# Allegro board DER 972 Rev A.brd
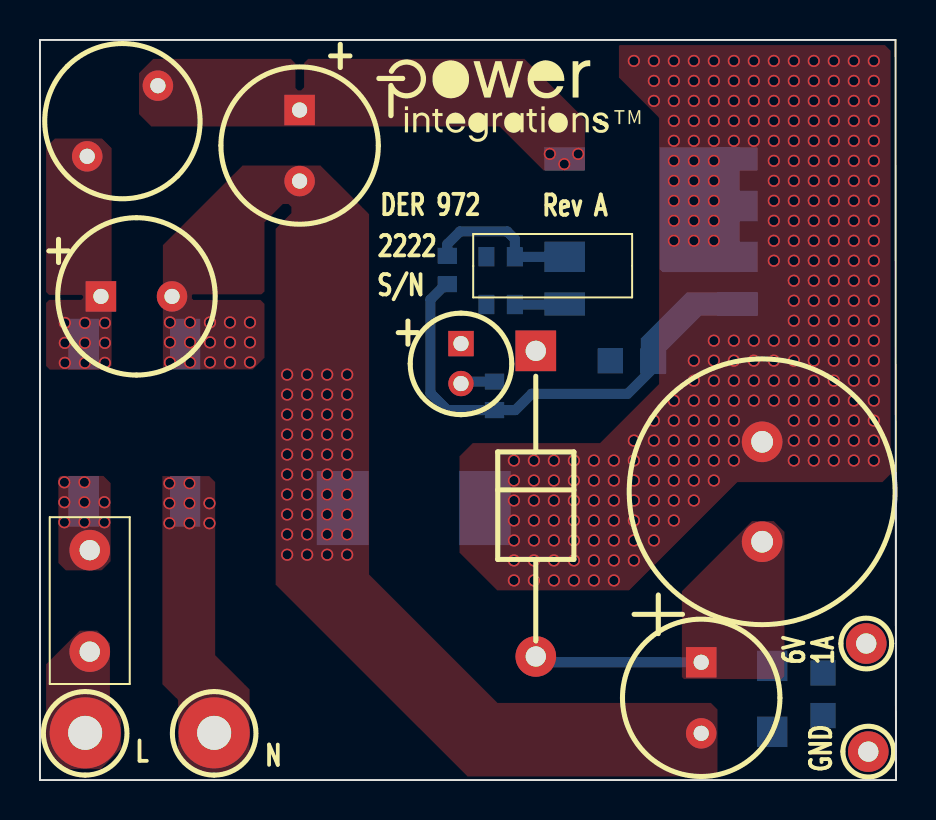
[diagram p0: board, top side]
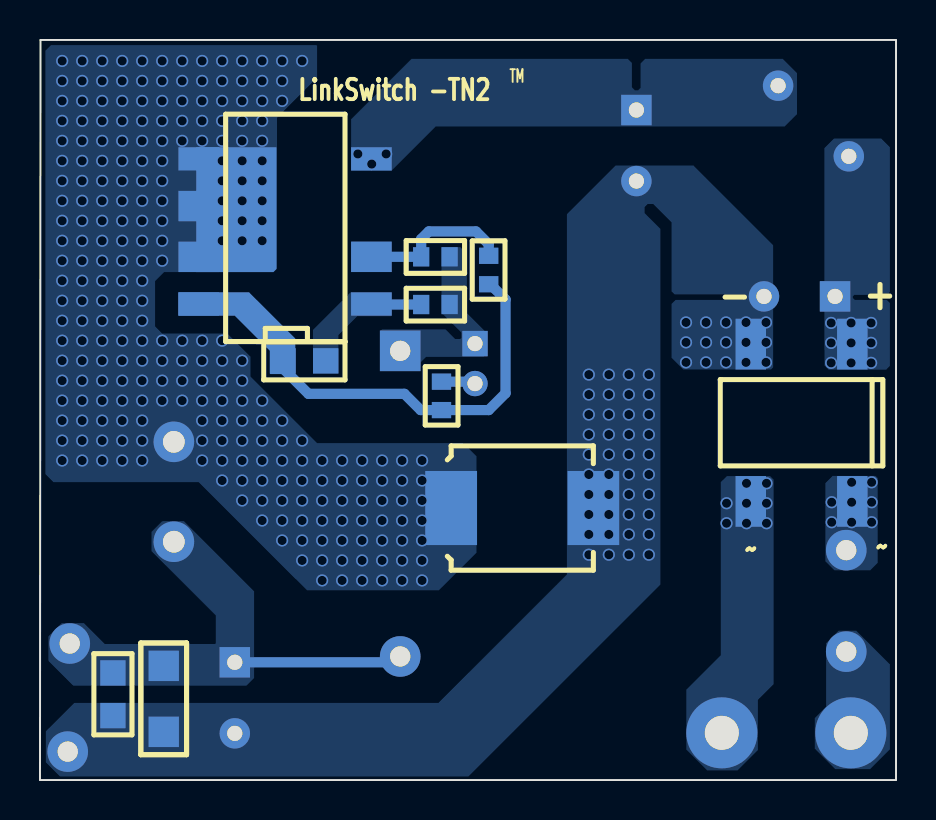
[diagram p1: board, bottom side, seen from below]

Outline 42.81 x 37.04 mm; copper layers: TOP, BOTTOM. Coordinates in mm from the lower left corner of the outline.
Outline path: 0,37.04 0,0 42.81,0 42.79,37.04 0,37.04

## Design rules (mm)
constraint set DEFAULT: min track width 0.508

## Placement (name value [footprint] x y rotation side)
BR1  DF06S-E3/45  [PISMDDFS]  2.18 21.77 180 bottom
C1  8.2 uF  [PIPOLCAPCLYD320LS140030]  3.05 24.21 0 top
C2  8.2 uF  [PIPOLCAPCLYD320LS140030]  12.99 33.53 270 top
C3  100 nF  [PISMC0805]  28.52 20.98 0 bottom
C4  10 uF  [PIPOLCAPCLYD200LS80030]  21.06 21.84 270 top
C5  330 uF  [PIPOLCAPCLYD320LS140030]  33.07 5.89 270 top
C6  100 nF  [PISMC1206]  36.63 5.71 270 bottom
D1  STTH3R06S  [PISMDO214AB12]  22.25 13.61 180 bottom
D2  BYV26C  [PIDV200X150X040SOD57]  24.8 21.48 270 top
F1  1 A  [PI_RST_MICROFUSE]  2.49 11.51 270 top
L1  470 uH  [PICHOKETOKINVD345H453LS197D030]  2.36 31.22 45 top
L2  330 uH  [PICHOKECOILCRFTD13P3H16LS5D043]  36.12 14.43 270 top
NOREF  -  []  -159.19 86.24 0 top
NOREF#2  -  []  0 0 90 top
NOREF#3  -  []  0 37.04 0 top
NOREF#4  -  []  16.84 36.5 0 top
NOREF#5  -  []  -228.6 -137.18 0 top
R1  2.49 k  [PISMR0603]  20.37 26.24 270 bottom
R2  5.36 k  [PISMR0603]  23.75 26.19 180 bottom
R3  3.48 k  [PISMR0603]  23.75 23.8 180 bottom
R4  10  [PISMR0603]  22.73 18.52 90 bottom
R5  20 k  [PISMR0805]  39.17 5.36 270 bottom
TP1  WHT  [PITPKEYSTONE125X125]  2.26 2.36 0 top
TP2  BLK  [PITPKEYSTONE125X125]  8.71 2.36 0 top
TP3  RED  [PITPKEYSTONE100X100]  41.33 6.83 270 top
TP4  BLK  [PITPKEYSTONE100X100]  41.43 1.42 270 top
U1  LNK3209G  [PIICSMD8CSHORT567IPC]  26.24 23.83 90 bottom

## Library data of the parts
BR1 = DIODE BRIDGE_+-~~
C1 C2 = CAP POL: alternate symbols: (pipolcapclyd320ls140030670h)
C3 C6 = CAP NP
C4 = CAP POL: alternate symbols: (pipolcapclyd200ls80030h)
C5 = CAP POL
D1 = DIODE
D2 = DIODE: alternate symbols: (pidax425x150040sod57,pidv200x150x040sod57r)
F1 = FUSE: alternate symbols: (pirstmicrofusehoz)
L1 = INDUCTOR: alternate symbols: (pichoketokinvd345h453ls197d030H)
L2 = INDUCTOR
R1-R5 = R
TP1-TP3 = TESTPOINT
TP4 = TESTPOINT: alternate symbols: (TP_TH_CR2_D1_1)
U1 = LNK32XX_8G

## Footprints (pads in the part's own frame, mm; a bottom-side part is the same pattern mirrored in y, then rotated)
PI_RST_MICROFUSE
  round 2.032 hole 1.016: 1(0,0) 2(5.08,0)
PICHOKECOILCRFTD13P3H16LS5D043
  round 2.032 hole 1.092: 1(-2.5,0) 2(2.5,0)
PICHOKETOKINVD345H453LS197D030
  round 1.524 hole 0.762: 1(0,0) 2(5,0)
PIDV200X150X040SOD57
  rect 2.032x2.032 hole 1.016: 1(0,0)
  round 2.032 hole 1.016: 2(15.296,0)
PIICSMD8CSHORT567IPC
  rect 1.168x2.032 smd: 1(0,0) 4(7.264,0) 5(7.264,8.636) 8(0,8.636)
  rect 1.524x2.032 smd: 2(2.362,0) 6(4.902,8.636) 7(2.362,8.636)
PIPOLCAPCLYD200LS80030
  rect 1.27x1.27 hole 0.762: 1(0,0)
  round 1.27 hole 0.762: 2(2,0)
PIPOLCAPCLYD320LS140030
  rect 1.524x1.524 hole 0.762: 1(0,0)
  round 1.524 hole 0.762: 2(3.556,0)
PISMC0805
  rect 1.27x1.27 smd: 1(0,0) 2(2.134,0)
PISMC1206
  rect 1.524x1.524 smd: 1(0,0) 2(3.302,0)
PISMDDFS
  rect 1.524x2.54 smd: 1(0,0.051) 2(-5.08,0.051) 3(0,-7.823) 4(-5.08,-7.823)
PISMDO214AB12
  rect 2.591x3.708 smd: 1(0,0) 2(7.112,0)
PISMR0603
  rect 0.813x0.965 smd: 1(0,0) 2(1.422,0)
PISMR0805
  rect 1.27x1.27 smd: 1(0,0) 2(2.134,0)
PITPKEYSTONE100X100
  round 2.032 hole 1.016: 1(0,0)
PITPKEYSTONE125X125
  round 3.556 hole 1.702: 1(0,0)

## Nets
N4183667: C2.1 L1.2 U1.4
N4183685: BR1.2 C1.2 C2.2 C5.2 C6.2 D1.2 R5.2 TP4.1
N4184589: C3.1 R3.1 U1.1
N4184987: D1.1 L2.1 U1.5 U1.6 U1.7
N4185002: C5.1 C6.1 D2.2 L2.2 R5.1 TP3.1
N4185015: C4.1 D2.1 R2.2 R3.2
N4189997: F1.2 TP1.1
N4191135: BR1.3 F1.1
N4191219: BR1.1 C1.1 L1.1
N4191500: BR1.4 TP2.1
N4228387: R1.1 R2.1 U1.2
N4235479: C3.2 R1.2 R4.1 U1.8
N4237461: C4.2 R4.2

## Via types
v1: diameter 0.61, hole 0.457, TOP to BOTTOM, 337 vias

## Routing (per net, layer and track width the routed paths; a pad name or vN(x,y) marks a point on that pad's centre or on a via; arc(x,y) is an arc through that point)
N4183667:
  vias: v1(25.5,31.34) v1(26.22,30.83) v1(26.92,31.34)
N4183685:
  vias: v1(6.5,22.9) v1(6.5,21.91) v1(6.5,20.9) v1(7.5,22.9) v1(7.5,21.91) v1(7.5,20.9) v1(8.5,22.9) v1(8.5,21.91) v1(8.5,20.9) v1(9.5,22.9) v1(9.5,21.91) v1(9.5,20.9) v1(10.5,22.9) v1(10.5,21.91) v1(10.5,20.9) v1(12.36,20.29) v1(12.36,19.29) v1(12.36,18.29) v1(12.36,17.29) v1(12.36,16.29) v1(12.36,15.29) v1(12.36,14.29) v1(12.36,13.29) v1(12.36,12.29) v1(12.36,11.28) v1(13.36,20.29) v1(13.36,19.29) v1(13.36,18.29) v1(13.36,17.29) v1(13.36,16.29) v1(13.36,15.29) v1(13.36,14.29) v1(13.36,13.29) v1(13.36,12.29) v1(13.36,11.28) v1(14.36,20.29) v1(14.36,19.29) v1(14.36,18.29) v1(14.36,17.29) v1(14.36,16.29) v1(14.36,15.29) v1(14.36,14.29) v1(14.36,13.29) v1(14.36,12.29) v1(14.36,11.28) v1(15.36,20.29) v1(15.36,19.29) v1(15.36,18.29) v1(15.36,17.29) v1(15.36,16.29) v1(15.36,15.29) v1(15.36,14.29) v1(15.36,13.29) v1(15.36,12.29) v1(15.36,11.28)
N4184589: length 3
  BOTTOM w0.508: 26.7,23.8 R3.1 23.72,23.8
N4184987:
  vias: v1(23.7,15.99) v1(23.7,14.99) v1(23.7,13.99) v1(23.7,12.99) v1(23.7,11.99) v1(23.7,10.99) v1(23.7,9.99) v1(24.7,15.99) v1(24.7,14.99) v1(24.7,13.99) v1(24.7,12.99) v1(24.7,11.99) v1(24.7,10.99) v1(24.7,9.99) v1(25.7,15.99) v1(25.7,14.99) v1(25.7,13.99) v1(25.7,12.99) v1(25.7,11.99) v1(25.7,10.99) v1(25.7,9.99) v1(26.7,15.99) v1(26.7,14.99) v1(26.7,13.99) v1(26.7,12.99) v1(26.7,11.99) v1(26.7,10.99) v1(26.7,9.99) v1(27.7,15.99) v1(27.7,14.99) v1(27.7,13.99) v1(27.7,12.99) v1(27.7,11.99) v1(27.7,10.99) v1(27.7,9.99) v1(28.7,15.99) v1(28.7,14.99) v1(28.7,13.99) v1(28.7,12.99) v1(28.7,11.99) v1(28.7,10.99) v1(28.7,9.99) v1(29.7,35.99) v1(29.7,16.99) v1(29.7,15.99) v1(29.7,14.99) v1(29.7,13.99) v1(29.7,12.99) v1(29.7,11.99) v1(29.7,10.99) v1(30.7,35.99) v1(30.7,34.99) v1(30.7,33.99) v1(30.7,17.99) v1(30.7,16.99) v1(30.7,15.99) v1(30.7,14.99) v1(30.7,13.99) v1(30.7,12.99) v1(30.7,11.99) v1(31.7,35.99) v1(31.7,34.99) v1(31.7,33.99) v1(31.7,32.99) v1(31.7,31.99) v1(31.7,30.99) v1(31.7,29.99) v1(31.7,28.99) v1(31.7,27.99) v1(31.7,26.99) v1(31.7,18.99) v1(31.7,17.99) v1(31.7,16.99) v1(31.7,15.99) v1(31.7,14.99) v1(31.7,13.99) v1(31.7,12.99) v1(32.7,35.99) v1(32.7,34.99) v1(32.7,33.99) v1(32.7,32.99) v1(32.7,31.99) v1(32.7,30.99) v1(32.7,29.99) v1(32.7,28.99) v1(32.7,27.99) v1(32.7,26.99) v1(32.7,20.99) v1(32.7,19.99) v1(32.7,18.99) v1(32.7,17.99) v1(32.7,16.99) v1(32.7,15.99) v1(32.7,14.99) v1(32.7,13.99) v1(33.7,35.99) v1(33.7,34.99) v1(33.7,33.99) v1(33.7,32.99) v1(33.7,31.99) v1(33.7,30.99) v1(33.7,29.99) v1(33.7,28.99) v1(33.7,27.99) v1(33.7,26.99) v1(33.7,21.99) v1(33.7,20.99) v1(33.7,19.99) v1(33.7,18.99) v1(33.7,17.99) v1(33.7,16.99) v1(33.7,15.99) v1(33.7,14.99) v1(34.7,35.99) v1(34.7,34.99) v1(34.7,33.99) v1(34.7,32.99) v1(34.7,31.99) v1(34.7,21.99) v1(34.7,20.99) v1(34.7,19.99) v1(34.7,18.99) v1(34.7,17.99) v1(34.7,16.99) v1(34.7,15.99) v1(35.7,35.99) v1(35.7,34.99) v1(35.7,33.99) v1(35.7,32.99) v1(35.7,31.99) v1(35.7,21.99) v1(35.7,20.99) v1(35.7,19.99) v1(35.7,18.99) v1(36.7,35.99) v1(36.7,34.99) v1(36.7,33.99) v1(36.7,32.99) v1(36.7,31.99) v1(36.7,30.99) v1(36.7,29.99) v1(36.7,28.99) v1(36.7,27.99) v1(36.7,26.99) v1(36.7,25.99) v1(36.7,21.99) v1(36.7,20.99) v1(36.7,19.99) v1(36.7,18.99) v1(37.7,35.99) v1(37.7,34.99) v1(37.7,33.99) v1(37.7,32.99) v1(37.7,31.99) v1(37.7,30.99) v1(37.7,29.99) v1(37.7,28.99) v1(37.7,27.99) v1(37.7,26.99) v1(37.7,25.99) v1(37.7,24.99) v1(37.7,23.99) v1(37.7,22.99) v1(37.7,21.99) v1(37.7,20.99) v1(37.7,19.99) v1(37.7,18.99) v1(37.7,17.99) v1(37.7,16.99) v1(37.7,15.99) v1(38.7,35.99) v1(38.7,34.99) v1(38.7,33.99) v1(38.7,32.99) v1(38.7,31.99) v1(38.7,30.99) v1(38.7,29.99) v1(38.7,28.99) v1(38.7,27.99) v1(38.7,26.99) v1(38.7,25.99) v1(38.7,24.99) v1(38.7,23.99) v1(38.7,22.99) v1(38.7,21.99) v1(38.7,20.99) v1(38.7,19.99) v1(38.7,18.99) v1(38.7,17.99) v1(38.7,16.99) v1(38.7,15.99) v1(39.7,35.99) v1(39.7,34.99) v1(39.7,33.99) v1(39.7,32.99) v1(39.7,31.99) v1(39.7,30.99) v1(39.7,29.99) v1(39.7,28.99) v1(39.7,27.99) v1(39.7,26.99) v1(39.7,25.99) v1(39.7,24.99) v1(39.7,23.99) v1(39.7,22.99) v1(39.7,21.99) v1(39.7,20.99) v1(39.7,19.99) v1(39.7,18.99) v1(39.7,17.99) v1(39.7,16.99) v1(39.7,15.99) v1(40.7,35.99) v1(40.7,34.99) v1(40.7,33.99) v1(40.7,32.99) v1(40.7,31.99) v1(40.7,30.99) v1(40.7,29.99) v1(40.7,28.99) v1(40.7,27.99) v1(40.7,26.99) v1(40.7,25.99) v1(40.7,24.99) v1(40.7,23.99) v1(40.7,22.99) v1(40.7,21.99) v1(40.7,20.99) v1(40.7,19.99) v1(40.7,18.99) v1(40.7,17.99) v1(40.7,16.99) v1(40.7,15.99) v1(41.7,35.99) v1(41.7,34.99) v1(41.7,33.99) v1(41.7,32.99) v1(41.7,31.99) v1(41.7,30.99) v1(41.7,29.99) v1(41.7,28.99) v1(41.7,27.99) v1(41.7,26.99) v1(41.7,25.99) v1(41.7,24.99) v1(41.7,23.99) v1(41.7,22.99) v1(41.7,21.99) v1(41.7,20.99) v1(41.7,19.99) v1(41.7,18.99) v1(41.7,17.99) v1(41.7,16.99) v1(41.7,15.99)
N4185002: length 8.4
  BOTTOM w0.508: C5.1 25.09,5.89 D2.2
N4191135:
  vias: v1(1.22,14.9) v1(1.22,13.9) v1(1.22,12.9) v1(2.22,14.9) v1(2.22,13.9) v1(2.22,12.9) v1(3.22,13.9) v1(3.22,12.9)
N4191219:
  vias: v1(1.24,22.88) v1(1.24,21.88) v1(1.24,20.88) v1(2.25,22.88) v1(2.25,21.88) v1(2.25,20.88) v1(3.24,22.88) v1(3.24,21.88) v1(3.24,20.88)
N4191500:
  vias: v1(6.48,14.85) v1(6.48,13.85) v1(6.48,12.85) v1(7.48,14.85) v1(7.48,13.85) v1(7.48,12.85) v1(8.48,13.85) v1(8.48,12.85)
N4228387: length 7.8
  BOTTOM w0.508: U1.2 R2.1 23.75,27.08 23.37,27.46 21.01,27.46 20.37,26.82 R1.1
N4235479: length 18.6
  BOTTOM w0.508: C3.2 30.66,20.6 29.39,19.33 24.59,19.33 23.77,18.52 R4.1 20.37,18.52 19.53,19.36 19.53,24.05 20.29,24.82 R1.2
N4237461: length 1.7
  BOTTOM w0.508: C4.2 21.15,19.94 R4.2

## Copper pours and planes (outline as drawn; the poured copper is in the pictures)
N4183667 on TOP: 27.25,33.07 24.23,36.09 24.13,36.09 24.13,36.09 23.6,36.09 23.59,36.09 13.41,36.09 13.21,35.89 13.21,34.67 13.06,34.52 12.9,34.52 12.78,34.65 12.78,35.86 12.55,36.09 5.66,36.09 4.95,35.38 4.95,33.32 5.57,32.71 22.99,32.71 25.2,30.5 26.59,30.5 26.59,30.51 27.25,30.51
N4183667 on BOTTOM: 27.25,30.51 27.25,33.07 24.23,36.09 13.41,36.09 13.21,35.89 13.21,34.67 13.06,34.52 12.9,34.52 12.78,34.65 12.78,35.86 12.55,36.09 5.66,36.09 4.95,35.38 4.95,33.32 5.57,32.71 23.01,32.71 25.22,30.51
N4183685 on TOP: 10.13,30.76 6.15,26.77 6.15,20.65 6.25,20.55 10.64,20.55 11.23,21.13 11.23,23.83 11.03,24.03 7.67,24.03 7.59,24.11 7.59,24.26 7.65,24.31 11.07,24.31 11.23,24.46 11.23,27.91 12.14,28.83 12.42,28.83 12.57,28.68 12.57,28.37 11.79,27.58 11.79,9.78 21.39,0.18 33.73,0.18 33.88,0.33 33.88,3.53 33.55,3.86 22.89,3.86 16.46,10.29 16.46,28.32 14.02,30.76
N4183685 on BOTTOM: 10.13,30.76 6.15,26.77 6.15,20.65 6.25,20.55 6.25,20.55 10.64,20.55 11.23,21.13 11.23,23.83 11.02,24.03 7.67,24.03 7.59,24.1 7.59,24.26 7.65,24.31 11.07,24.31 11.23,24.46 11.23,27.91 12.14,28.83 12.42,28.83 12.57,28.68 12.57,28.37 11.79,27.58 11.79,9.78 21.39,0.18 41.81,0.18 42.52,0.89 42.52,2.44 41.1,3.86 22.89,3.86 16.46,10.29 16.46,28.32 14.02,30.76
N4184589 on BOTTOM: 27.28,24.41 25.22,24.41 25.22,23.24 25.25,23.22 26.95,23.22 27.89,22.28 27.89,20.35 29.16,20.35 29.16,22.53
N4184987 on BOTTOM (solid shape): 35,25.43 31.14,25.43 30.99,25.58 30.99,31.67 35,31.67
N4184987 on TOP: 28.96,36.75 28.96,35.15 30.96,33.15 30.96,19.81 28.02,16.87 21.64,16.87 20.98,16.21 20.98,11.38 22.86,9.5 29.46,9.5 34.87,14.91 42.14,14.91 42.55,15.32 42.55,36.5 42.27,36.78 28.98,36.78
N4184987 on BOTTOM: 28.96,36.75 28.96,35.15 30.96,33.15 30.96,25.6 31.14,25.43 36.6,25.43 37.06,24.97 37.06,22.71 36.7,22.35 33.45,22.35 32.28,21.18 32.28,20.19 28.96,16.87 21.64,16.87 20.98,16.21 20.98,11.38 22.86,9.5 29.46,9.5 34.87,14.91 42.14,14.91 42.55,15.32 42.55,36.5 42.27,36.78 28.98,36.78
N4185002 on TOP: 32.11,9.45 32.11,5.16 32.21,5.05 37.08,5.05 37.24,5.21 37.24,12.42 36.7,12.95 35.61,12.95
N4185002 on BOTTOM: 41.15,4.72 42.39,5.97 42.39,7.19 41.73,7.85 40.61,7.85 39.57,6.81 34.06,6.81 34.02,6.85 34.02,8.24 37.24,11.46 37.24,12.42 36.7,12.95 35.61,12.95 32.11,9.45 32.11,5.11 32.49,4.72
N4185015 on BOTTOM: 20.52,21.29 20.52,22.43 21.46,23.37 21.46,26.34 21.79,26.67 22.73,26.67 22.73,23.39 21.74,22.4 21.74,22.12 21.79,22.07 22.05,22.07 22.53,22.56 25.7,22.56 25.78,22.48 25.78,20.73 25.73,20.68 24,20.68 23.5,21.18 20.62,21.18
N4189997 on TOP, BOTTOM: 2.87,7.47 3.49,6.85 3.49,3.67 4.06,3.1 4.06,1.57 3.04,0.55 1.3,0.55 0.3,1.54 0.3,5.79 1.99,7.47
N4191135 on TOP, BOTTOM: 1.02,15.22 0.92,15.12 0.92,10.87 1.29,10.5 3.08,10.5 3.53,10.95 3.53,14.86 3.17,15.22
N4191219 on TOP: 0.5,20.54 0.3,20.73 0.3,23.88 0.46,24.03 2.06,24.03 2.16,24.13 2.16,24.21 2.08,24.28 0.46,24.28 0.3,24.43 0.3,31.67 0.74,32.11 3.1,32.11 3.58,31.62 3.58,20.75 3.37,20.54
N4191219 on BOTTOM: 0.5,20.54 0.3,20.73 0.3,23.88 0.46,24.03 2.06,24.03 2.16,24.13 2.16,24.21 2.08,24.28 0.46,24.28 0.3,24.43 0.3,31.67 0.74,32.11 3.1,32.11 3.58,31.62 3.58,21.5 3.57,21.49 3.57,20.75 3.37,20.54
N4191500 on TOP: 6.12,15.21 6.12,4.8 6.91,4.01 6.91,1.24 7.77,0.38 9.76,0.38 10.49,1.12 10.49,4.52 8.76,6.25 8.76,14.91 8.46,15.21
N4191500 on BOTTOM: 6.3,15.21 6.12,15.04 6.12,4.8 6.91,4.01 6.91,1.5 7.92,0.48 9.45,0.48 10.49,1.52 10.49,4.52 8.76,6.25 8.76,14.91 8.46,15.21
N4235479 on BOTTOM (solid shape): 35.89,23.24 33.07,23.24 31.32,21.49 31.32,20.35 31.29,20.32 30.05,20.32 30.05,22.1 32.36,24.41 35.89,24.41

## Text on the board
Ref Des/Silkscreen Bottom: TM | LinkSwitch -TN2
Ref Des/Silkscreen Top: L | N | S/N | 2222 | DER 972 | Rev A | 6V | GND | 1A
User.6: 14.  FAB HOUSE LOGO,DATE CODE TO BE IN SILK SCREEN ONLY.DO NOT USE COPPER. | 13.  MATERIAL FR4 COPPER 2oz THICKNESS 0.039"
User.8: FIGURE | FINISHED_SIZE | 18.0 | 30.0 | 40.0 | 43.0 | 67.0 | DRILL CHART: TOP to BOTTOM | ALL UNITS ARE IN MILS | TOLERANCE_DRILL | +3.0/-3.0 | PLATED | QTY | 345 | 10 | 6 | 2 | 365 | TOTAL HOLES:
